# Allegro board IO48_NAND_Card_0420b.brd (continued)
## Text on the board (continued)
User.20: FIGURE | SIZE | 8.0 | 12.0 | 24.0 | 35.0 | 40.0 | 45.0 | 50.0 | 62.0 | 79.0 | 125.0 | 128.0 | 33.46 | 67.0 | 95.0 | DRILL CHART: TOP to BOTTOM | ALL UNITS ARE IN MILS | TOLERANCE | +3.0/-3.0 | +2.0/-2.0 | +0.0/-0.0 | PLATED | NON-PLATED | QTY | 51 | 505 | 5 | 12 | 2 | 9 | 3 | 4
